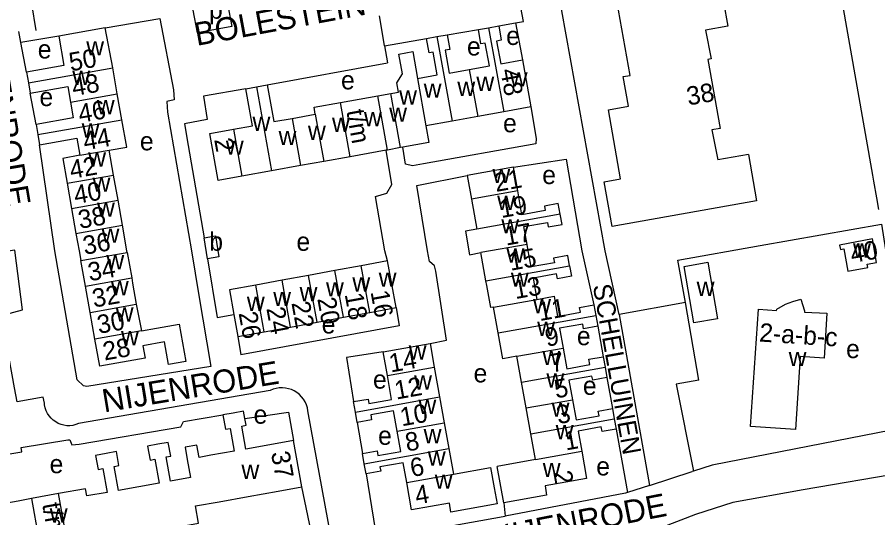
# Model space of a CAD drawing. Extents: x 157794 to 159375, y 380877 to 382306.
# Drawn here: x 158601.4 to 158787.7, y 381442.2 to 381550.6 of the extents above; entities that cross this region are included whole.
import ezdxf

# ---------------------------------------------------------------- set-up
doc = ezdxf.new("R2010")
doc.units = 0
for name, color, linetype in [('BLT_Basislijn', 7, 'Continuous'), ('BLT_Bebouwing', 7, 'Continuous'), ('BLT_Centroide', 7, 'Continuous'), ('BLT_Huisnummer', 7, 'Continuous'), ('BLT_Huisnummer_ tussenligend', 7, 'Continuous'), ('BLT_Huisnummer_reeks', 7, 'Continuous'), ('BLT_Onderdoorgang_en_onderverdeling', 7, 'Continuous'), ('BLT_Onderverdeling_panden', 7, 'Continuous'), ('BLT_Straatnaam', 7, 'Continuous'), ('BLT_Straatnaam_verkleind', 7, 'Continuous')]:
    doc.layers.add(name, color=color, linetype=linetype)

msp = doc.modelspace()

# ---------------------------------------------------------------- linework, layer by layer
at = {"layer": 'BLT_Basislijn'}
for p, q in [((158605.58, 381547.69), (158604.58, 381553.46)), ((158646.98, 381553.45), (158647.89, 381548.54)), ((158640.46, 381547.16), (158639.55, 381552.07)), ((158705.65, 381548.7), (158709.29, 381549.36)), ((158709.29, 381549.36), (158710.79, 381541.31)), ((158602.26, 381545.06), (158601.81, 381547.46)), ((158647.89, 381548.54), (158640.46, 381547.16)), ((158694.51, 381546.79), (158701.25, 381547.9)), ((158610.44, 381546.47), (158602.26, 381545.06)), ((158603.47, 381538.66), (158602.26, 381545.06)), ((158680.95, 381544.34), (158690.02, 381545.98)), ((158680.95, 381544.34), (158681.61, 381540.66)), ((158655.54, 381535.94), (158681.61, 381540.66)), ((158605.52, 381527.36), (158604.27, 381534.15)), ((158650.89, 381535.1), (158641.74, 381533.45)), ((158641.74, 381533.45), (158642.58, 381528.4)), ((158642.58, 381528.4), (158637.62, 381527.51)), ((158637.62, 381527.51), (158638.47, 381522.78)), ((158638.47, 381522.78), (158641.87, 381502.78)), ((158762.21, 381501.13), (158788.5, 381505.74)), ((158744.38, 381498), (158762.21, 381501.13)), ((158642.65, 381498.28), (158644.69, 381485.55)), ((158746.09, 381488.83), (158744.38, 381498)), ((158640.78, 381490.3), (158643.34, 381474.98)), ((158683.45, 381487.7), (158684.11, 381483.77)), ((158746.09, 381488.83), (158731.74, 381486.25)), ((158748.93, 381471.99), (158746.09, 381488.83)), ((158644.69, 381485.55), (158648.33, 381486.21)), ((158731.74, 381486.25), (158738.27, 381449.21)), ((158684.11, 381483.77), (158649.86, 381477.49)), ((158727.08, 381483.7), (158728.27, 381477.07)), ((158649.21, 381481.42), (158649.86, 381477.49)), ((158680.63, 381478.14), (158676.03, 381477.41)), ((158729.07, 381472.57), (158730.26, 381465.84)), ((158748.93, 381471.99), (158744.07, 381471.12)), ((158744.07, 381471.12), (158747.8, 381452.3)), ((158656.22, 381469.77), (158614.74, 381462.6)), ((158670.01, 381434.5), (158664.36, 381465.38)), ((158675.02, 381462.86), (158676.15, 381456.12)), ((158731.06, 381461.41), (158733.53, 381447.68)), ((158738.27, 381449.21), (158747.54, 381452.22)), ((158747.8, 381452.3), (158747.54, 381452.22)), ((158665.85, 381435.67), (158663.05, 381448.94)), ((158738.27, 381449.21), (158733.53, 381447.68)), ((158706.72, 381445.47), (158707.06, 381442.56))]:
    msp.add_line(p, q, dxfattribs=at)
for points in [[(158786.85, 381515.06), (158786.62, 381516.36), (158776.43, 381574.23)], [(158709.29, 381549.36), (158710.98, 381549.66), (158709.75, 381556.17)], [(158731.74, 381486.25), (158728.66, 381500), (158719.31, 381551.96), (158718.87, 381553.92), (158718.53, 381554.37), (158714.98, 381555.3)], [(158680.95, 381544.34), (158680.93, 381544.47), (158679.81, 381550.84)], [(158620.5, 381548.24), (158632.29, 381550.3), (158635.25, 381534.86), (158635.42, 381532.69)], [(158635.42, 381532.69), (158633.84, 381532.34), (158633.97, 381530.03), (158639.16, 381500), (158640.78, 381490.3)], [(158712.62, 381531.16), (158713.77, 381524.32), (158713.69, 381523.18), (158689.37, 381518.84), (158686.96, 381518.39), (158685.47, 381518.78), (158684.86, 381522.43)], [(158643.34, 381474.98), (158616.48, 381470.61), (158615.78, 381470.78), (158614.41, 381472.04), (158609.61, 381500), (158606.3, 381522.94)], [(158679, 381511.74), (158681.4, 381512.48), (158682.51, 381514.33), (158681.27, 381521.78)], [(158708.83, 381518.12), (158720.22, 381519.84), (158723.63, 381500), (158726.26, 381488.31)], [(158690.78, 381479.96), (158694.31, 381480.68), (158692.02, 381495.6), (158691.75, 381496.72), (158690.65, 381497.71), (158690.24, 381500), (158687.96, 381514.16), (158698.81, 381516.32)], [(158787.94, 381508.94), (158787.5, 381511.47), (158786.85, 381515.06)], [(158681.6, 381497.81), (158681.03, 381500), (158679, 381511.74)], [(158788.5, 381505.74), (158795.12, 381463.28), (158793.64, 381461.75), (158751.87, 381453.61), (158747.8, 381452.3)], [(158602.61, 381487.22), (158600.91, 381500.16), (158597.47, 381499.62)], [(158600.86, 381470.34), (158598.07, 381486.03), (158602.61, 381487.22)], [(158676.03, 381477.41), (158672.72, 381476.89), (158674.21, 381467.35)], [(158607.33, 381467.05), (158607.08, 381468.29), (158601.4, 381467.3), (158600.86, 381470.34)], [(158664.36, 381465.38), (158664.23, 381466.04), (158664.03, 381466.69), (158663.75, 381467.3), (158663.4, 381467.88), (158662.98, 381468.41), (158662.51, 381468.89), (158661.98, 381469.31), (158661.4, 381469.66), (158660.79, 381469.95), (158660.15, 381470.16), (158659.49, 381470.29), (158658.82, 381470.34), (158658.14, 381470.31), (158657.47, 381470.21), (158656.83, 381470.02), (158656.22, 381469.77)], [(158614.74, 381462.6), (158614.13, 381462.38), (158613.5, 381462.22), (158612.86, 381462.15), (158612.21, 381462.15), (158611.56, 381462.24), (158610.94, 381462.4), (158610.33, 381462.64), (158609.77, 381462.96), (158609.24, 381463.33), (158608.77, 381463.78), (158608.35, 381464.27), (158607.99, 381464.82), (158607.71, 381465.4), (158607.5, 381466.01), (158607.37, 381466.65), (158607.33, 381467.05)], [(158650.72, 381463.69), (158660.16, 381465.08), (158661.25, 381458.91)], [(158602.29, 381457.43), (158612.41, 381459.11), (158612.86, 381459.11), (158613.27, 381458.01), (158614.85, 381458.17), (158636.83, 381461.91), (158637.44, 381463.07), (158645.93, 381464.47)], [(158588.21, 381454.13), (158602.43, 381456.51), (158602.29, 381457.43)], [(158793.51, 381451.98), (158771.53, 381448.28), (158756.34, 381445.5), (158748.25, 381442.91), (158740.95, 381440.08), (158735.85, 381438.89)], [(158676.94, 381451.71), (158678.92, 381439.71), (158679.5, 381438.09), (158680.45, 381437.79), (158706.62, 381442.48), (158707.06, 381442.56)], [(158733.53, 381447.68), (158733.09, 381447.54), (158707.06, 381442.56)]]:
    msp.add_lwpolyline(points, dxfattribs=at)
at = {"layer": 'BLT_Bebouwing'}
for p, q in [((158703.45, 381548.3), (158705.65, 381548.7)), ((158620.5, 381548.24), (158610.44, 381546.47)), ((158622.1, 381539.63), (158620.5, 381548.24)), ((158692.26, 381546.38), (158694.51, 381546.79)), ((158701.25, 381547.9), (158703.45, 381548.3)), ((158690.02, 381545.98), (158692.26, 381546.38)), ((158710.79, 381541.31), (158712.62, 381531.16)), ((158623.1, 381533.98), (158622.1, 381539.63)), ((158603.47, 381538.66), (158603.87, 381536.4)), ((158603.87, 381536.4), (158604.27, 381534.15)), ((158653.21, 381535.52), (158655.54, 381535.94)), ((158624.1, 381528.37), (158623.1, 381533.98)), ((158650.89, 381535.1), (158653.21, 381535.52)), ((158679.47, 381533.56), (158682.29, 381534.07)), ((158682.29, 381534.07), (158682.74, 381534.15)), ((158665.68, 381531.07), (158671.37, 381532.1)), ((158671.37, 381532.1), (158679.47, 381533.56)), ((158665.95, 381529.58), (158665.68, 381531.07)), ((158706.74, 381530.1), (158701.12, 381529.08)), ((158712.62, 381531.16), (158706.74, 381530.1)), ((158660.93, 381528.67), (158665.95, 381529.58)), ((158701.12, 381529.08), (158695.57, 381528.08)), ((158605.52, 381527.36), (158605.91, 381525.15)), ((158643.12, 381525.42), (158648.22, 381526.34)), ((158695.57, 381528.08), (158689.9, 381527.06)), ((158605.91, 381525.15), (158606.3, 381522.94)), ((158751.79, 381526.2), (158753.03, 381519.69)), ((158622.3, 381516.39), (158621.34, 381521.8)), ((158681.27, 381521.78), (158673.48, 381520.37)), ((158681.59, 381521.82), (158681.27, 381521.78)), ((158684.4, 381522.34), (158681.59, 381521.82)), ((158684.86, 381522.43), (158684.4, 381522.34)), ((158759.69, 381520.87), (158753.03, 381519.69)), ((158667.79, 381519.35), (158662.78, 381518.44)), ((158673.48, 381520.37), (158667.79, 381519.35)), ((158656.5, 381517.31), (158650.07, 381516.15)), ((158662.78, 381518.44), (158656.5, 381517.31)), ((158708.83, 381518.12), (158698.81, 381516.32)), ((158709.75, 381512.96), (158708.83, 381518.12)), ((158623.26, 381510.97), (158622.3, 381516.39)), ((158698.81, 381516.32), (158699.73, 381511.17)), ((158612.25, 381514.61), (158613.2, 381509.19)), ((158624.22, 381505.55), (158623.26, 381510.97)), ((158699.73, 381511.17), (158700.89, 381504.72)), ((158613.2, 381509.19), (158614.16, 381503.77)), ((158642.65, 381498.28), (158641.87, 381502.78)), ((158625.26, 381499.67), (158626.22, 381494.14)), ((158702.87, 381493.51), (158701.8, 381499.61)), ((158616.2, 381492.33), (158615.2, 381497.94)), ((158675.9, 381496.76), (158670.19, 381495.72)), ((158681.6, 381497.81), (158675.9, 381496.76)), ((158664.48, 381494.67), (158658.77, 381493.62)), ((158670.19, 381495.72), (158664.48, 381494.67)), ((158658.77, 381493.62), (158653.06, 381492.58)), ((158617.23, 381486.62), (158616.2, 381492.33)), ((158653.06, 381492.58), (158647.35, 381491.53)), ((158647.35, 381491.53), (158648.33, 381486.21)), ((158704.54, 381487.81), (158713.92, 381489.49)), ((158627.22, 381488.45), (158628.32, 381482.68)), ((158705.49, 381482.25), (158704.54, 381487.81)), ((158726.26, 381488.31), (158726.67, 381486)), ((158618.25, 381480.91), (158617.23, 381486.62)), ((158669.09, 381485.06), (158672.04, 381485.61)), ((158672.04, 381485.61), (158677.75, 381486.65)), ((158726.67, 381486), (158727.08, 381483.7)), ((158654.92, 381482.47), (158660.62, 381483.51)), ((158660.62, 381483.51), (158666.33, 381484.56)), ((158666.33, 381484.56), (158669.09, 381485.06)), ((158680.63, 381478.14), (158690.78, 381479.96)), ((158690.78, 381479.96), (158691.7, 381474.8)), ((158681.55, 381472.99), (158680.63, 381478.14)), ((158710.59, 381471.58), (158709.59, 381477.17)), ((158728.27, 381477.07), (158728.67, 381474.82)), ((158691.7, 381474.8), (158692.85, 381468.38)), ((158728.67, 381474.82), (158729.07, 381472.57)), ((158711.59, 381465.99), (158710.59, 381471.58)), ((158674.62, 381465.11), (158674.21, 381467.35)), ((158692.85, 381468.38), (158693.85, 381462.8)), ((158648.18, 381464.88), (158645.93, 381464.47)), ((158675.02, 381462.86), (158674.62, 381465.11)), ((158712.59, 381460.4), (158711.59, 381465.99)), ((158730.26, 381465.84), (158730.66, 381463.63)), ((158730.66, 381463.63), (158731.06, 381461.41)), ((158693.85, 381462.8), (158694.85, 381457.2)), ((158713.59, 381454.8), (158712.59, 381460.4)), ((158661.25, 381458.91), (158656.09, 381457.98)), ((158663.05, 381448.94), (158661.25, 381458.91)), ((158676.55, 381453.92), (158676.15, 381456.12)), ((158694.85, 381457.2), (158695.85, 381451.64)), ((158676.94, 381451.71), (158676.55, 381453.92)), ((158713.59, 381454.8), (158705.32, 381453.3)), ((158706.72, 381445.47), (158705.32, 381453.3)), ((158657.9, 381448.01), (158663.05, 381448.94)), ((158645.12, 381445.7), (158651.44, 381446.84)), ((158651.44, 381446.84), (158657.9, 381448.01)), ((158640.04, 381444.78), (158645.12, 381445.7))]:
    msp.add_line(p, q, dxfattribs=at)
for points in [[(158748.07, 381567.91), (158749.74, 381558.48), (158753.36, 381559.12), (158755.22, 381548.64), (158750.43, 381547.79)], [(158732.03, 381515.6), (158729.38, 381530.51), (158733.71, 381531.28), (158732.57, 381537.7), (158734.06, 381537.97), (158731.19, 381554.1), (158721.76, 381552.43), (158721.24, 381555.36), (158719.47, 381555.05)], [(158705.65, 381548.7), (158706.21, 381545.59), (158705.18, 381545.4), (158706.08, 381540.46), (158710.79, 381541.31)], [(158694.51, 381546.79), (158695.08, 381543.61), (158694.05, 381543.43), (158694.94, 381538.46), (158699.28, 381539.25)], [(158699.28, 381539.25), (158703.63, 381540.04), (158702.74, 381544.97), (158701.81, 381544.8), (158701.25, 381547.9)], [(158750.43, 381547.79), (158751.6, 381541.54), (158750.91, 381541.42), (158753.55, 381526.51)], [(158610.44, 381546.47), (158611.56, 381540.09), (158603.47, 381538.66)], [(158688.08, 381537.31), (158692.36, 381538.08), (158691.47, 381543.01), (158690.58, 381542.85), (158690.02, 381545.98)], [(158682.74, 381534.15), (158683.95, 381534.37), (158683.59, 381536.34), (158684.81, 381538.31), (158684.04, 381542.58), (158687.03, 381543.12), (158688.08, 381537.31)], [(158604.27, 381534.15), (158612.37, 381535.58), (158612.97, 381532.19)], [(158655.54, 381535.94), (158656.98, 381527.96), (158660.93, 381528.67)], [(158648.22, 381526.34), (158652.33, 381527.08), (158650.89, 381535.1)], [(158612.97, 381532.19), (158613.57, 381528.78), (158605.52, 381527.36)], [(158621.34, 381521.8), (158625.14, 381522.47), (158624.1, 381528.37)], [(158689.9, 381527.06), (158690.55, 381523.46), (158684.86, 381522.43)], [(158753.55, 381526.51), (158751.79, 381526.2)], [(158650.07, 381516.15), (158644.96, 381515.23), (158643.12, 381525.42)], [(158606.3, 381522.94), (158614.38, 381524.36), (158615.03, 381520.68)], [(158615.03, 381520.68), (158611.29, 381520.02), (158612.25, 381514.61)], [(158759.69, 381520.87), (158761.45, 381510.83), (158730.21, 381505.27), (158728.43, 381514.97), (158732.03, 381515.6)], [(158718.93, 381507.95), (158718.53, 381510.21), (158715.54, 381509.67), (158715.72, 381508.71), (158710.68, 381507.8), (158709.75, 381512.96)], [(158711.77, 381501.4), (158711.09, 381505.25), (158716.18, 381506.16), (158716.36, 381505.16), (158719.34, 381505.69), (158718.93, 381507.95)], [(158625.26, 381499.67), (158625.2, 381500), (158624.22, 381505.55)], [(158700.89, 381504.72), (158698.45, 381504.29), (158699.33, 381499.14), (158701.8, 381499.61)], [(158614.16, 381503.77), (158614.83, 381500), (158615.2, 381497.94)], [(158641.87, 381502.78), (158644.33, 381503.23), (158645.11, 381498.73), (158642.65, 381498.28)], [(158720.99, 381496.75), (158720.59, 381498.99), (158717.51, 381498.44), (158717.69, 381497.41), (158712.64, 381496.51), (158712.03, 381500), (158711.77, 381501.4)], [(158683.45, 381487.7), (158681.6, 381497.81)], [(158720.99, 381496.75), (158721.4, 381494.49), (158718.37, 381493.95), (158718.18, 381494.99), (158713.1, 381494.08), (158713.92, 381489.49)], [(158626.22, 381494.14), (158626.42, 381493.01), (158627.22, 381488.45)], [(158704.54, 381487.81), (158703.91, 381487.7), (158703.05, 381492.48), (158702.87, 381493.51)], [(158713.92, 381489.49), (158717.61, 381490.15), (158718.38, 381485.82), (158723.35, 381486.71), (158723.16, 381487.75), (158726.26, 381488.31)], [(158761.9, 381487.35), (158765.79, 381487.06), (158765.84, 381487.4), (158767.74, 381488.44), (158769.28, 381489.05), (158771.01, 381489.56), (158771.79, 381486.99), (158771.8, 381486.74), (158776.62, 381486.5), (158776.06, 381476.73), (158770.91, 381477.1), (158769.88, 381461.35), (158760.15, 381461.99), (158761.9, 381487.35)], [(158677.75, 381486.65), (158683.45, 381487.7)], [(158648.33, 381486.21), (158649.21, 381481.42)], [(158628.32, 381482.68), (158631.57, 381483.25), (158636.5, 381484.11), (158637.91, 381476.04), (158634.19, 381475.38), (158633.33, 381480.27), (158628.63, 381479.44), (158629.11, 381476.74), (158619.31, 381475.02), (158618.25, 381480.91)], [(158727.08, 381483.7), (158724, 381483.15), (158723.82, 381484.16), (158718.83, 381483.26), (158719.6, 381478.96)], [(158649.21, 381481.42), (158654.92, 381482.47)], [(158709.59, 381477.17), (158706.5, 381476.63), (158705.49, 381482.25)], [(158719.6, 381478.96), (158720.4, 381474.49), (158725.38, 381475.38), (158725.18, 381476.52), (158728.27, 381477.07)], [(158674.21, 381467.35), (158677.36, 381467.92), (158677.53, 381466.96), (158682.47, 381467.84), (158681.55, 381472.99)], [(158729.07, 381472.57), (158725.98, 381472.02), (158725.83, 381472.89), (158720.85, 381472), (158721.6, 381467.78)], [(158721.6, 381467.78), (158722.39, 381463.39), (158727.37, 381464.28), (158727.19, 381465.29), (158730.26, 381465.84)], [(158650.72, 381463.69), (158650.43, 381465.28), (158648.18, 381464.88)], [(158683.68, 381460.98), (158682.89, 381465.38), (158677.95, 381464.49), (158678.14, 381463.42), (158675.02, 381462.86)], [(158645.93, 381464.47), (158646.49, 381461.39), (158647.51, 381461.57), (158648.39, 381456.66), (158643.31, 381455.74)], [(158656.09, 381457.98), (158650.94, 381457.04), (158650.03, 381462.06), (158650.98, 381462.23), (158650.72, 381463.69)], [(158731.06, 381461.41), (158728.03, 381460.87), (158727.85, 381461.87), (158722.84, 381460.97), (158723.62, 381456.6)], [(158676.15, 381456.12), (158679.34, 381456.7), (158679.52, 381455.69), (158684.47, 381456.58), (158683.68, 381460.98)], [(158631.9, 381458.14), (158629.65, 381457.73), (158630.2, 381454.7), (158631.21, 381454.88), (158632.15, 381449.71), (158627.76, 381448.92)], [(158638.93, 381450.93), (158634.6, 381450.15), (158633.65, 381455.38), (158634.68, 381455.57), (158634.14, 381458.54), (158631.9, 381458.14)], [(158643.31, 381455.74), (158640.79, 381455.29), (158640.31, 381457.93), (158637.82, 381457.48), (158638.23, 381454.82), (158638.93, 381450.93)], [(158620.66, 381456.13), (158618.42, 381455.72), (158618.97, 381452.68), (158619.95, 381452.86), (158620.88, 381447.72), (158616.5, 381446.93)], [(158627.76, 381448.92), (158623.38, 381448.12), (158622.43, 381453.35), (158623.45, 381453.53), (158622.91, 381456.53), (158620.66, 381456.13)], [(158723.62, 381456.6), (158724.67, 381450.75), (158715.67, 381449.13), (158716.02, 381447.14), (158706.72, 381445.47)], [(158685.74, 381449.83), (158684.96, 381454.14), (158679.94, 381453.24), (158680.11, 381452.28), (158676.94, 381451.71)], [(158601.66, 381445.82), (158597.94, 381445.15), (158597.69, 381446.68), (158595.89, 381448.02), (158595.1, 381452.97), (158592.08, 381452.49), (158593.02, 381446.59)], [(158695.85, 381451.64), (158703.9, 381453.08), (158704.69, 381448.68), (158705.31, 381445.23), (158695.31, 381443.45), (158694.96, 381445.41), (158686.79, 381443.94), (158685.74, 381449.83)], [(158616.5, 381446.93), (158616.21, 381448.51), (158610.37, 381447.45)], [(158604.52, 381446.39), (158601.66, 381445.82)], [(158610.37, 381447.45), (158604.52, 381446.39)], [(158635.17, 381440.06), (158640.71, 381441.06), (158640.04, 381444.78)]]:
    msp.add_lwpolyline(points, dxfattribs=at)
for points in [[(158786.5, 381502.62), (158779.42, 381501.21), (158779.58, 381500.27), (158780.32, 381500.41), (158781.18, 381495.6), (158785.52, 381496.41), (158785.39, 381497.1), (158787.43, 381497.49)], [(158745.81, 381496.64), (158750.93, 381497.52), (158753.02, 381485.29), (158747.9, 381484.42)]]:
    msp.add_lwpolyline(points, close=True, dxfattribs=at)
at = {"layer": 'BLT_Onderdoorgang_en_onderverdeling'}
msp.add_line((158681.59, 381521.82), (158679.47, 381533.56), dxfattribs=at)
msp.add_lwpolyline([(158684.4, 381522.34), (158682.29, 381534.07)], dxfattribs=at)
at = {"layer": 'BLT_Onderverdeling_panden'}
for p, q in [((158703.45, 381548.3), (158706.74, 381530.1)), ((158692.26, 381546.38), (158695.57, 381528.08)), ((158603.87, 381536.4), (158622.1, 381539.63)), ((158699.28, 381539.25), (158701.12, 381529.08)), ((158688.08, 381537.31), (158689.9, 381527.06)), ((158612.97, 381532.19), (158623.1, 381533.98)), ((158653.21, 381535.52), (158656.5, 381517.31)), ((158673.48, 381520.37), (158671.37, 381532.1)), ((158605.91, 381525.15), (158624.1, 381528.37)), ((158660.93, 381528.67), (158662.78, 381518.44)), ((158665.95, 381529.58), (158667.79, 381519.35)), ((158648.22, 381526.34), (158650.07, 381516.15)), ((158615.03, 381520.68), (158621.34, 381521.8)), ((158612.25, 381514.61), (158622.3, 381516.39)), ((158709.75, 381512.96), (158699.73, 381511.17)), ((158613.2, 381509.19), (158623.26, 381510.97)), ((158718.93, 381507.95), (158700.89, 381504.72)), ((158614.16, 381503.77), (158624.22, 381505.55)), ((158711.77, 381501.4), (158701.8, 381499.61)), ((158615.2, 381497.94), (158625.26, 381499.67)), ((158677.75, 381486.65), (158675.9, 381496.76)), ((158702.87, 381493.51), (158720.99, 381496.75)), ((158666.33, 381484.56), (158664.48, 381494.67)), ((158672.04, 381485.61), (158670.19, 381495.72)), ((158616.2, 381492.33), (158626.22, 381494.14)), ((158660.62, 381483.51), (158658.77, 381493.62)), ((158654.92, 381482.47), (158653.06, 381492.58)), ((158617.23, 381486.62), (158627.22, 381488.45)), ((158705.49, 381482.25), (158726.67, 381486)), ((158628.32, 381482.68), (158618.25, 381480.91)), ((158709.59, 381477.17), (158719.6, 381478.96)), ((158681.55, 381472.99), (158691.7, 381474.8)), ((158710.59, 381471.58), (158728.67, 381474.82)), ((158674.62, 381465.11), (158692.85, 381468.38)), ((158711.59, 381465.99), (158721.6, 381467.78)), ((158712.59, 381460.4), (158730.66, 381463.63)), ((158683.68, 381460.98), (158693.85, 381462.8)), ((158676.55, 381453.92), (158694.85, 381457.2)), ((158713.59, 381454.8), (158723.62, 381456.6)), ((158685.74, 381449.83), (158695.85, 381451.64)), ((158604.52, 381446.39), (158606.6, 381434.89)), ((158612.45, 381435.95), (158610.37, 381447.45))]:
    msp.add_line(p, q, dxfattribs=at)

# ---------------------------------------------------------------- texts
at = {"layer": 'BLT_Centroide'}
for s, p in [('p', (158642.95, 381550.24)), ('e', (158707.25, 381544.56)), ('w', (158616.38, 381542.31)), ('e', (158698.78, 381542.28)), ('e', (158605.89, 381541.64)), ('w', (158613.36, 381535.91)), ('e', (158671.52, 381534.95)), ('w', (158700.81, 381534.62)), ('w', (158708.03, 381535.58)), ('w', (158689.41, 381533.14)), ('w', (158696.69, 381533.53)), ('e', (158606.26, 381531.33)), ('w', (158684.09, 381531.65)), ('w', (158618.66, 381529.56)), ('w', (158676.48, 381526.97)), ('w', (158681.94, 381527.94)), ('w', (158652.36, 381525.97)), ('w', (158669.58, 381525.72)), ('e', (158706.59, 381525.66)), ('w', (158615.4, 381524.53)), ('w', (158664.36, 381524)), ('e', (158627.99, 381521.75)), ('w', (158658, 381522.88)), ('w', (158646.59, 381520.78)), ('w', (158616.79, 381518.22)), ('w', (158704.28, 381514.66)), ('e', (158715.06, 381514.45)), ('w', (158617.75, 381512.78)), ('w', (158705.32, 381508.84)), ('w', (158618.71, 381507.38)), ('w', (158706.2, 381503.78)), ('w', (158619.7, 381501.75)), ('b', (158643.01, 381500.01)), ('e', (158661.87, 381500.01)), ('w', (158707.32, 381497.44)), ('w', (158782.32, 381498.55)), ('w', (158620.73, 381496)), ('w', (158679.67, 381492.23)), ('w', (158708.27, 381492.22)), ('w', (158621.71, 381490.38)), ('w', (158668.27, 381490.14)), ('w', (158673.97, 381491.19)), ('w', (158748.48, 381490.23)), ('w', (158656.84, 381488.05)), ('w', (158662.55, 381489.09)), ('w', (158651.14, 381487)), ('w', (158713.09, 381486.47)), ('w', (158622.76, 381484.69)), ('e', (158667.34, 381482.11)), ('w', (158713.97, 381481.59)), ('w', (158623.91, 381479.56)), ('e', (158722.56, 381479.58)), ('e', (158780.82, 381476.78)), ('w', (158686.16, 381476.47)), ('w', (158715.09, 381475.28)), ('w', (158768.39, 381475.06)), ('e', (158700.2, 381471.52)), ('e', (158678.44, 381470.17)), ('w', (158687.34, 381469.97)), ('w', (158715.97, 381470.41)), ('e', (158723.86, 381468.82)), ('w', (158688.27, 381464.69)), ('w', (158717.1, 381464.09)), ('e', (158652.6, 381462.58)), ('e', (158679.54, 381458.01)), ('w', (158689.4, 381458.34)), ('w', (158717.98, 381459.22)), ('w', (158690.3, 381453.5)), ('e', (158608.45, 381451.86)), ('w', (158649.97, 381450.62)), ('w', (158715.17, 381451.03)), ('e', (158726.75, 381451.38)), ('w', (158691.8, 381448.5)), ('w', (158608.48, 381441.16))]:
    msp.add_text(s, height=4, dxfattribs=at).set_placement(p)
at = {"layer": 'BLT_Huisnummer'}
for s, rotation, p in [('50', 10.0433, (158613.02, 381538.84)), ('38', 10.0726, (158746.68, 381531.44)), ('44', 9.9536, (158616.07, 381521.73)), ('21', 10.1494, (158705.07, 381512.74)), ('40', 9.9536, (158614.06, 381510.1)), ('17', 10.1494, (158707.24, 381501.12)), ('36', 9.9536, (158616.02, 381499.13)), ('40', 10.0726, (158782.11, 381497.34)), ('13', 10.1494, (158709.25, 381489.54)), ('32', 9.9536, (158618.04, 381487.7)), ('16', 280.3861, (158677.89, 381491.13)), ('20', 280.3906, (158666.37, 381489.63)), ('26', 280.3906, (158649.34, 381486.52)), ('9', 10.1494, (158716.03, 381479.23)), ('28', 9.9536, (158620.33, 381476.24)), ('14', 10.1399, (158682.28, 381473.65)), ('5', 10.1494, (158718.03, 381468.04)), ('8', 10.1506, (158685.78, 381456.54)), ('1', 10.1494, (158720.18, 381456.77)), ('2', 280.1546, (158717.44, 381452.1)), ('4', 10.1522, (158687.89, 381445.06))]:
    msp.add_text(s, height=4, rotation=rotation, dxfattribs=at).set_placement(p)
at = {"layer": 'BLT_Huisnummer_ tussenligend'}
for s, rotation, p in [('48', 9.9536, (158613.63, 381533.47)), ('46', 9.9536, (158615.02, 381527.69)), ('42', 9.9536, (158613.14, 381515.55)), ('19', 10.1494, (158706.2, 381507.08)), ('38', 9.9536, (158615, 381504.74)), ('15', 10.1494, (158708.2, 381495.67)), ('34', 9.9536, (158617.1, 381493.4)), ('22', 280.3906, (158660.77, 381488.74)), ('18', 280.3861, (158672.3, 381490.59)), ('11', 10.1494, (158714.51, 381484.78)), ('24', 280.3906, (158655.35, 381487.53)), ('30', 9.9536, (158619.09, 381482.02)), ('7', 10.1494, (158717.14, 381473.64)), ('12', 10.1506, (158683.46, 381467.79)), ('10', 10.1506, (158684.67, 381462)), ('3', 10.1494, (158718.52, 381462.47)), ('6', 10.1522, (158686.84, 381451.02))]:
    msp.add_text(s, height=4, rotation=rotation, dxfattribs=at).set_placement(p)
at = {"layer": 'BLT_Huisnummer_reeks'}
for s, rotation, p in [('48', 280.2317, (158705.97, 381539.13)), ('t/m', 280.2347, (158672.65, 381530.28)), ('2', 280.2346, (158644.06, 381524.09)), ('2-a-b-c', 356.2606, (158761.93, 381480.38)), ('37', 280.2439, (158656.35, 381456.29)), ('t/m', 280.2574, (158606.84, 381445.15))]:
    msp.add_text(s, height=4, rotation=rotation, dxfattribs=at).set_placement(p)
at = {"layer": 'BLT_Straatnaam'}
for s, rotation, p in [('BOLESTEIN', 10.4764, (158640.3, 381544.35)), ('NIJENRODE', 279.5371, (158593.07, 381547.47)), ('NIJENRODE', 9.376, (158620.25, 381465)), ('NIJENRODE', 11.1107, (158704.38, 381435.22))]:
    msp.add_text(s, height=5, rotation=rotation, dxfattribs=at).set_placement(p)
at = {"layer": 'BLT_Straatnaam_verkleind'}
msp.add_text('SCHELLUINEN', height=4, rotation=280.166, dxfattribs=at).set_placement((158725.99, 381492.48))

doc.saveas('drawing.dxf')
